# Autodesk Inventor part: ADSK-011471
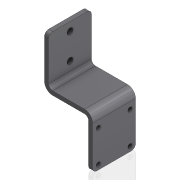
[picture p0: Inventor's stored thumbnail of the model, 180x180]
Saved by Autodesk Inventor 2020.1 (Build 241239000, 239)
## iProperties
Created: 2000-01
Part Number: ADSK-011471
Material: 1.0312 DC05
Description: FSHTPH,FH,CV,057,025,028,090,SUPPORT,TRAY_TRANSFER
Document SubType Name: Tôlerie
Designer: cmcgourin
Density: 1 g/cm^3
Sheet Metal Rule: Stahlblech 1.0312 - DC05 -   6.0 mm
Appearance: Metal-Steel(Polish)
Mass: 75.8801 g
Surface Area: 292.525 cm^2
Volume: 75.8801 cm^3
Flat Pattern Width: 6.35 cm
Flat Pattern Length: 20.2573 cm
Flat Pattern Area: 128.634 cm^2
Sheet Metal Width: 63,500 mm
Sheet Metal Length: 202,573 mm
Sheet Metal Area: 12863,383 mm^2
Control State: 0
Checked Out: False
Master: False
Shininess: 25.0
Length Units: 11269
Angle Units: 11279
Time Units: 11290
Mass Units: 11283
Length Display Precision: 3
Angle Display Precision: 2
Compacted: True
Cutlength: 7.95
Material Desc: FLAT,HRS,0.25 X 02.500
Material_Number: A084330
G_L: 202,6x63,5 mm
Thickness: 6,000 mm
Dimensions: 71,4x146x63,5 mm
Mass: 0,076 kg
Semi finished: Stahlblech 1.0312 - DC05 -   6.0 mm
DocNumber: ADSK-011471.ipt
Folder: 01 - Themengebiete\Simplification\01 - Packaging machine\
VDS_Category: 3D Komponenten
Density: 7.829999999999999
Volumn: 79.87074036474914
Area: 293.93026758719367
PropertySet Name: Model Information
Author: cmcgourin
Revision Number: -
Title: angle
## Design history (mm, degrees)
node "Solide1"
  node "Face2"
  node "Flange1"
  node "Flange2"
  node "Corner Round1" dims "d49" = 6.35
  node "Hole4" dims "d58" = 6.35, "d59" = 9.525, "d60" = 6.35, "d61" = 60 deg, "d62" = 19.05, "d63" = 118 deg
sketch "Sketch12"
  geometry: L1 (6.35, 63.85)-(57.15, 63.85) reference; L2 (31.75, 51.35)-(31.75, 13.35); 3 further points
  constraints: 2 coincident, 2 end point, 1 midpoint, 1 vertical, 1 vertical alignment
  dimensions: "d72" = 12.5 distance from line of L1 point (31.75, 51.35); "d73" = 38 distance of L2.start L2.end
hole "Bohrung5" sketch "Sketch12" at (31.75, 51.35), (31.75, 13.35) diameter "d74" = 9; stored, may be unused: countersink angle "d78" = 90 deg, drill point angle "d80" = 118 deg; dims "d75" = 16, "d76" = 17.3, "d77" = 2, "d79" = 6 (= Thickness)
node "Plate2" dims "d70" = 6 (= Thickness)
node "Plate3" dims "d45" = 6 (= BendRadius), "d70" = 6 (= Thickness), "MinimumRemnant" = 12 (= 2 x Thickness), "BendReliefWidth" = 6 (= Thickness)
node "Bend2" dims "d45" = 6 (= BendRadius), "d64" = 6 (= BendReliefWidth), "d65" = 3 (= BendReliefDepth), "d66" = 12 (= MinimumRemnant), "d70" = 6 (= Thickness), "SeamGap" = 0.00508, "MinimumRemnant" = 12 (= 2 x Thickness), "BendReliefWidth" = 6 (= Thickness)
node "Plate4" dims "d48" = 6 (= BendRadius), "d70" = 6 (= Thickness), "MinimumRemnant" = 12 (= 2 x Thickness), "BendReliefWidth" = 6 (= Thickness)
node "Bend3" dims "d48" = 6 (= BendRadius), "d67" = 6 (= BendReliefWidth), "d68" = 3 (= BendReliefDepth), "d69" = 12 (= MinimumRemnant), "d70" = 6 (= Thickness), "SeamGap" = 0.00508, "MinimumRemnant" = 12 (= 2 x Thickness), "BendReliefWidth" = 6 (= Thickness)
node "Corps solides"
node "Corps surfaciques"
sketch "Sketch9"
  geometry: L1 (0, 0)-(-76.2, 0); L2 (-76.2, 0)-(-76.2, 63.5); L3 (-76.2, 63.5)-(0, 63.5); L4 (0, 63.5)-(0, 0)
  constraints: 8 end point, 2 parallel, 1 horizontal, 1 perpendicular
  dimensions: "d40" = 63.5 distance of L1.end L2.end; "d41" = 76.2 distance of L2.end L3.end
sketch "Sketch10"
  geometry: L1 (0.35, 0)-(-71.38, 0); L2 (-71.38, 63.5)-(0.35, 63.5); 1 other entity
  constraints: 2 horizontal, 2 vertical alignment
  dimensions: "d43" = 71.7296 distance of L1.start L1.end; "d43" = 71.7296 distance of L2.end L2.start
sketch "Sketch11"
  geometry: L1 (-0.35, 63.5)-(75.85, 63.5); L2 (75.85, 0)-(-0.35, 0); 1 other entity
  constraints: 2 horizontal, 2 vertical alignment
  dimensions: "d46" = 76.2 distance of L1.start L1.end; "d46" = 76.2 distance of L2.end L2.start
sketch "Sketch15"
  geometry: C1 r 2.458 at (8.247, -10) reference; C2 r 2.458 at (55.247, -10) reference; C3 r 2.458 at (55.247, -57) reference; C4 r 2.458 at (8.247, -57) reference
feature "Definition1"
other parameters: "Thickness" = 6 (derived), "BendRadius" = 6 (= Thickness), "BendReliefDepth" = 3 (= 0.5 x Thickness), "CornerReliefSize" = 24 (= 4 x Thickness), "d42" = 6 (= BendRadius), "d44" = 90 deg, "d47" = 90 deg, "TransitionRadius" = 6 (= BendRadius), "TailleRayonJacobi" = 6 (= BendRadius), "TailleJeu" = 6 (= Thickness), "BendRadius" = 6, "BendReliefDepth" = 3, "BendReliefWidth" = 6, "CornerReliefSize" = 24, "MinimumRemnant" = 12, "TailleJeu" = 6, "TailleRayonJacobi" = 6, "Thickness" = 6, "TransitionRadius" = 6
